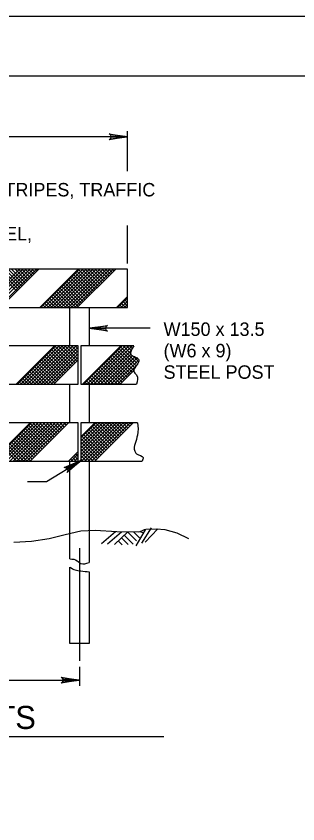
# Model space of a CAD drawing. Extents: x -4 to 901, y -468 to 720.
# Drawn here: x 256.4 to 326.8, y 518.1 to 720 of the extents above; entities that cross this region are included whole.
import ezdxf

# ---------------------------------------------------------------- set-up
doc = ezdxf.new("R2010")
doc.units = 0
for name, color, linetype in [('1', 7, 'Continuous'), ('2', 7, 'Continuous'), ('3', 7, 'Continuous'), ('PLT-BNDY', 7, 'Continuous')]:
    doc.layers.add(name, color=color, linetype=linetype)

msp = doc.modelspace()

# ---------------------------------------------------------------- linework, layer by layer
at = {"layer": '1'}
msp.add_lwpolyline([(822.258, 141.027875), (822.258, 705.027875), (36.258, 705.027875), (36.258, 141.027875), (822.258, 141.027875), (822.258, 167.386875), (622.258, 167.386875), (622.258, 232.064375), (822.258, 232.064375), (822.258, 261.027875), (622.258, 261.027875), (622.258, 141.027875), (701.0595, 141.027875), (701.0595, 167.386875), (701.0595, 141.027875), (778.0595, 141.027875), (778.0595, 167.386875), (778.0595, 155.070375), (822.258, 155.070375)], dxfattribs=at)
at = {"layer": '2'}
for p, q in [((284.2805, 681.251125), (284.2805, 691.305125)), ((284.2805, 689.865125), (140.2805, 689.865125)), ((284.2805, 658.235125), (284.2805, 667.691125)), ((252.5145, 647.195125), (262.1145, 656.795125)), ((262.34125, 647.205125), (271.94125, 656.805125)), ((262.34125, 647.205125), (271.94125, 656.805125)), ((271.7145, 647.195125), (281.3145, 656.795125)), ((281.54125, 647.205125), (284.2805, 649.944375)), ((256.45525, 628.005125), (266.05525, 637.605125)), ((273.00925, 627.995125), (282.60925, 637.595125)), ((265.8285, 627.995125), (271.9685, 634.135125)), ((282.3925, 627.995125), (285.9105, 631.513125)), ((250.3425, 608.795125), (259.9425, 618.395125)), ((259.9425, 608.795125), (269.5425, 618.395125)), ((272.5945, 614.881125), (276.1085, 618.395125)), ((276.1085, 608.795125), (285.7085, 618.395125)), ((269.5425, 608.795125), (271.9685, 611.221125)), ((287.8245, 588.247125), (290.2225, 592.081125)), ((288.6925, 588.561125), (291.8045, 591.841125)), ((277.7945, 588.217125), (281.2285, 591.195125)), ((279.2945, 588.111125), (282.7465, 591.105125)), ((281.0225, 587.963125), (284.3045, 591.143125)), ((282.7425, 589.629125), (284.4085, 587.909125)), ((283.4445, 590.309125), (285.6385, 588.047125)), ((284.2345, 591.145125), (286.4785, 588.829125)), ((285.7885, 591.121125), (287.2525, 589.611125)), ((286.4345, 587.607125), (288.7305, 591.587125)), ((287.3565, 591.177125), (288.3065, 590.855125)), ((281.9525, 588.865125), (282.9045, 587.881125)), ((272.2805, 587.057125), (272.2805, 558.835125)), ((272.2805, 557.395125), (272.2805, 552.577125)), ((152.2805, 554.017125), (272.2805, 554.017125))]:
    msp.add_line(p, q, dxfattribs=at)
for points in [[(279.9205, 690.413125), (280.0845, 690.097125), (284.2805, 689.865125), (279.9205, 690.413125), (279.6985, 690.603125), (284.2805, 689.865125), (280.0865, 689.657125), (279.9345, 689.345125), (284.2805, 689.865125), (279.6985, 689.137125), (279.9345, 689.345125)], [(247.66775, 647.195125), (257.26775, 656.795125)], [(248.51625, 647.195125), (258.11625, 656.795125)], [(249.36475, 647.195125), (258.96475, 656.795125)], [(250.21325, 647.195125), (259.81325, 656.795125)], [(251.06225, 647.195125), (260.66225, 656.795125)], [(251.91075, 647.195125), (261.51075, 656.795125)], [(256.99525, 651.693625), (252.32075, 656.386125)], [(257.42025, 652.117125), (252.74575, 656.809625)], [(257.84525, 652.540625), (253.607, 656.795125)], [(258.27025, 652.964125), (254.454, 656.795125)], [(258.6955, 653.387625), (255.30125, 656.795125)], [(259.1205, 653.810875), (256.14775, 656.795125)], [(259.5455, 654.234375), (256.99475, 656.795125)], [(259.97075, 654.657875), (257.84175, 656.795125)], [(260.39575, 655.081375), (258.6885, 656.795125)], [(260.82075, 655.504625), (259.53525, 656.795125)], [(261.246, 655.928125), (260.38225, 656.795125)], [(261.671, 656.351625), (261.21925, 656.805125)], [(262.63525, 647.205125), (272.23525, 656.805125)], [(262.63525, 647.205125), (272.23525, 656.805125)], [(263.47375, 647.195125), (273.07375, 656.795125)], [(264.32225, 647.195125), (273.92225, 656.795125)], [(265.17075, 647.195125), (274.77075, 656.795125)], [(266.01925, 647.195125), (275.61925, 656.795125)], [(266.86775, 647.195125), (276.46775, 656.795125)], [(267.71625, 647.195125), (277.31625, 656.795125)], [(268.56475, 647.195125), (278.16475, 656.795125)], [(269.41325, 647.195125), (279.01325, 656.795125)], [(270.26225, 647.195125), (279.86225, 656.795125)], [(271.11075, 647.195125), (280.71075, 656.795125)], [(276.19525, 651.693625), (271.5215, 656.385375)], [(276.62025, 652.117125), (271.9605, 656.795125)], [(277.04525, 652.540625), (272.80725, 656.795125)], [(277.47025, 652.964125), (273.654, 656.795125)], [(277.8955, 653.387625), (274.50125, 656.795125)], [(278.3205, 653.810875), (275.34775, 656.795125)], [(278.7455, 654.234375), (276.19475, 656.795125)], [(279.17075, 654.657875), (277.04175, 656.795125)], [(279.59575, 655.081375), (277.8885, 656.795125)], [(280.02075, 655.504625), (278.73525, 656.795125)], [(280.446, 655.928125), (279.58225, 656.795125)], [(280.871, 656.351625), (280.41925, 656.805125)], [(256.57, 651.270125), (251.8955, 655.962625)], [(274.06975, 649.576375), (269.396, 654.268125)], [(274.495, 649.999875), (269.82125, 654.691625)], [(274.92, 650.423375), (270.24625, 655.115125)], [(275.345, 650.846625), (270.67125, 655.538375)], [(275.77025, 651.270125), (271.0965, 655.961875)], [(272.3695, 647.882625), (267.69575, 652.574375)], [(272.7945, 648.306125), (268.12075, 652.997875)], [(273.21975, 648.729375), (268.546, 653.421125)], [(273.64475, 649.152875), (268.971, 653.844625)], [(268.82, 647.195125), (265.5705, 650.457125)], [(269.66675, 647.195125), (265.9955, 650.880625)], [(270.51375, 647.195125), (266.4205, 651.304125)], [(271.3605, 647.195125), (266.84575, 651.727375)], [(271.9445, 647.459125), (267.27075, 652.150875)], [(264.58525, 647.195125), (263.445, 648.339875)], [(265.43225, 647.195125), (263.87, 648.763375)], [(266.27925, 647.195125), (264.29525, 649.186875)], [(267.126, 647.195125), (264.72025, 649.610125)], [(267.97275, 647.195125), (265.14525, 650.033625)], [(281.83525, 647.205125), (284.2805, 649.650375)], [(283.76325, 647.205125), (282.65125, 648.315125)], [(283.76325, 647.205125), (282.65125, 648.315125)], [(282.68325, 647.205125), (284.2805, 648.802125)], [(284.2805, 647.535375), (283.07525, 648.739125)], [(284.2805, 648.384625), (283.50125, 649.163125)], [(284.2805, 649.233875), (283.92525, 649.589125)], [(262.89125, 647.195125), (262.59475, 647.492875)], [(263.7385, 647.195125), (263.02, 647.916375)], [(269.8805, 637.595125), (269.8805, 647.195125), (274.6805, 647.195125), (274.6805, 637.595125)], [(282.06725, 647.205125), (281.80325, 647.467125)], [(282.06725, 647.205125), (281.80325, 647.467125)], [(282.91525, 647.205125), (282.22725, 647.891125)], [(282.91525, 647.205125), (282.22725, 647.891125)], [(283.53125, 647.205125), (284.2805, 647.954375)], [(279.0405, 641.457125), (278.8765, 641.773125), (274.6805, 642.005125), (279.0405, 641.457125), (279.2625, 641.267125), (274.6805, 642.005125), (278.8745, 642.213125), (279.0265, 642.525125), (274.6805, 642.005125), (279.2625, 642.733125), (279.0265, 642.525125)], [(289.882, 642.005125), (274.6805, 642.005125)], [(256.74925, 628.005125), (266.34925, 637.605125)], [(256.74925, 628.005125), (266.34925, 637.605125)], [(257.58775, 627.995125), (267.18775, 637.595125)], [(258.43625, 627.995125), (268.03625, 637.595125)], [(259.28475, 627.995125), (268.88475, 637.595125)], [(260.13325, 627.995125), (269.73325, 637.595125)], [(260.98175, 627.995125), (270.58175, 637.595125)], [(261.83025, 627.995125), (271.43025, 637.595125)], [(262.67875, 627.995125), (271.9685, 637.284875)], [(263.52725, 627.995125), (271.9685, 636.436375)], [(269.47075, 631.637125), (264.779, 636.328875)], [(269.895, 632.061375), (265.20325, 636.753125)], [(270.31925, 632.485625), (265.6275, 637.177375)], [(270.7435, 632.909875), (266.05175, 637.601625)], [(271.1675, 633.334375), (266.90675, 637.595125)], [(271.592, 633.758375), (267.75525, 637.595125)], [(271.9685, 634.230375), (268.60375, 637.595125)], [(271.9685, 635.078875), (269.45225, 637.595125)], [(271.9685, 635.927375), (270.30075, 637.595125)], [(271.9685, 636.775875), (271.13925, 637.605125)], [(285.8245, 637.595125), (272.5945, 637.595125), (272.5945, 627.995125), (286.5225, 627.995125)], [(273.30325, 627.995125), (282.90325, 637.595125)], [(274.15175, 627.995125), (283.75175, 637.595125)], [(275.00025, 627.995125), (284.60025, 637.595125)], [(275.84875, 627.995125), (285.44875, 637.595125)], [(276.69725, 627.995125), (285.187, 636.484875)], [(285.8695, 631.481875), (281.16525, 636.172875)], [(286.109, 632.090375), (281.589, 636.597625)], [(286.3495, 632.697625), (282.01275, 637.022375)], [(286.60025, 633.295125), (282.43625, 637.447375)], [(285.11625, 635.622375), (283.13775, 637.595125)], [(285.17225, 636.413875), (283.98775, 637.595125)], [(285.37275, 637.061125), (284.83725, 637.595125)], [(285.744, 637.538375), (285.687, 637.595125)], [(267.3495, 629.515875), (262.65775, 634.207625)], [(267.77375, 629.940125), (263.082, 634.631875)], [(268.198, 630.364375), (263.50625, 635.056125)], [(268.62225, 630.788625), (263.9305, 635.480375)], [(269.0465, 631.212875), (264.35475, 635.904625)], [(264.37625, 627.995125), (271.9685, 635.587375)], [(265.22475, 627.995125), (271.9685, 634.738875)], [(277.54575, 627.995125), (285.1185, 635.567875)], [(278.39425, 627.995125), (285.516, 635.116875)], [(283.75125, 629.357375), (279.047, 634.048375)], [(279.24275, 627.995125), (286.16125, 634.913625)], [(284.175, 629.782375), (279.47075, 634.473375)], [(284.5985, 630.207125), (279.89425, 634.898125)], [(280.09125, 627.995125), (286.7775, 634.681375)], [(285.02225, 630.632125), (280.318, 635.323125)], [(285.446, 631.056875), (280.74175, 635.747875)], [(286.845, 633.898375), (285.682, 635.057875)], [(264.62725, 627.995125), (260.53625, 632.086125)], [(265.47575, 627.995125), (260.9605, 632.510375)], [(266.0765, 628.242875), (261.38475, 632.934625)], [(266.50075, 628.667125), (261.809, 633.358875)], [(266.925, 629.091375), (262.23325, 633.783125)], [(281.71825, 627.995125), (277.35225, 632.348875)], [(282.48025, 628.082875), (277.776, 632.773875)], [(282.904, 628.507625), (278.19975, 633.198625)], [(283.3275, 628.932625), (278.62325, 633.623625)], [(280.94025, 627.995125), (286.846, 633.900875)], [(281.78875, 627.995125), (286.25225, 632.458625)], [(261.23325, 627.995125), (258.83925, 630.389125)], [(262.08175, 627.995125), (259.2635, 630.813375)], [(262.93025, 627.995125), (259.68775, 631.237625)], [(263.77875, 627.995125), (260.112, 631.661875)], [(277.46975, 627.995125), (275.234, 630.224625)], [(278.31925, 627.995125), (275.6575, 630.649375)], [(279.16925, 627.995125), (276.08125, 631.074375)], [(280.019, 627.995125), (276.505, 631.499125)], [(280.8685, 627.995125), (276.9285, 631.924125)], [(256.99075, 627.995125), (256.718, 628.267875)], [(257.83925, 627.995125), (257.14225, 628.692125)], [(258.68775, 627.995125), (257.5665, 629.116375)], [(259.53625, 627.995125), (257.99075, 629.540625)], [(260.38475, 627.995125), (258.415, 629.964875)], [(269.8805, 618.395125), (269.8805, 627.995125)], [(274.07075, 627.995125), (273.53925, 628.525125)], [(274.9205, 627.995125), (273.963, 628.949875)], [(275.77025, 627.995125), (274.3865, 629.374875)], [(274.6805, 627.995125), (274.6805, 618.395125)], [(276.61975, 627.995125), (274.81025, 629.799625)], [(250.635, 608.795125), (260.237, 618.395125)], [(251.4835, 608.795125), (261.0855, 618.395125)], [(252.33225, 608.795125), (261.93425, 618.395125)], [(253.181, 608.795125), (262.783, 618.395125)], [(254.0295, 608.795125), (263.6315, 618.395125)], [(254.878, 608.795125), (264.48, 618.395125)], [(255.7265, 608.795125), (265.3285, 618.395125)], [(256.57525, 608.795125), (266.17725, 618.395125)], [(257.424, 608.795125), (267.026, 618.395125)], [(258.2725, 608.795125), (267.8745, 618.395125)], [(259.12125, 608.795125), (268.72325, 618.395125)], [(264.2245, 613.077125), (259.4245, 617.877125)], [(264.64875, 613.501375), (259.84875, 618.301375)], [(265.073, 613.925625), (260.6035, 618.395125)], [(265.49725, 614.349875), (261.452, 618.395125)], [(265.92175, 614.774375), (262.301, 618.395125)], [(266.346, 615.198625), (263.1495, 618.395125)], [(266.77025, 615.622875), (263.998, 618.395125)], [(267.1945, 616.047125), (264.8465, 618.395125)], [(267.61875, 616.471375), (265.695, 618.395125)], [(268.043, 616.895625), (266.5435, 618.395125)], [(268.46725, 617.319875), (267.392, 618.395125)], [(268.8915, 617.744125), (268.2405, 618.395125)], [(269.31575, 618.168375), (269.089, 618.395125)], [(286.7545, 618.395125), (272.5945, 618.395125), (272.5945, 608.795125), (287.9145, 608.795125)], [(272.5945, 614.596375), (276.3945, 618.395125)], [(272.5945, 613.748125), (277.24325, 618.395125)], [(272.5945, 612.899375), (278.092, 618.395125)], [(272.5945, 612.051375), (278.9405, 618.395125)], [(272.5945, 609.505875), (281.4865, 618.395125)], [(272.5945, 610.354625), (280.638, 618.395125)], [(272.5945, 611.203125), (279.789, 618.395125)], [(272.73175, 608.795125), (282.335, 618.395125)], [(273.58075, 608.795125), (283.18375, 618.395125)], [(274.42925, 608.795125), (284.0325, 618.395125)], [(275.278, 608.795125), (284.88125, 618.395125)], [(280.56275, 613.247125), (275.7605, 618.047125)], [(280.987, 613.671375), (276.261, 618.395125)], [(281.411, 614.095875), (277.1095, 618.395125)], [(281.83525, 614.520125), (277.95825, 618.395125)], [(282.2595, 614.944625), (278.80725, 618.395125)], [(282.6835, 615.368875), (279.65575, 618.395125)], [(283.10775, 615.793375), (280.50475, 618.395125)], [(283.532, 616.217625), (281.35325, 618.395125)], [(283.956, 616.642125), (282.202, 618.395125)], [(284.38025, 617.066375), (283.05075, 618.395125)], [(284.80425, 617.490875), (283.8995, 618.395125)], [(285.2285, 617.915125), (284.74825, 618.395125)], [(262.5275, 611.380125), (257.7275, 616.180125)], [(262.95175, 611.804375), (258.15175, 616.604375)], [(263.376, 612.228625), (258.576, 617.028625)], [(263.80025, 612.652875), (259.00025, 617.452875)], [(278.442, 611.125375), (273.63975, 615.925375)], [(278.866, 611.549625), (274.06375, 616.349625)], [(279.29025, 611.974125), (274.488, 616.774125)], [(279.7145, 612.398375), (274.91225, 617.198375)], [(280.1385, 612.822875), (275.33625, 617.622875)], [(260.406, 609.258625), (255.606, 614.058625)], [(260.83025, 609.682875), (256.03025, 614.482875)], [(261.25475, 610.107375), (256.45475, 614.907375)], [(261.679, 610.531625), (256.879, 615.331625)], [(262.10325, 610.955875), (257.30325, 615.755875)], [(277.1695, 609.852125), (272.5945, 614.424875)], [(277.5935, 610.276625), (272.79125, 615.076625)], [(278.01775, 610.700875), (273.2155, 615.500875)], [(256.627, 608.795125), (253.48475, 611.937375)], [(257.4755, 608.795125), (253.909, 612.361625)], [(258.324, 608.795125), (254.33325, 612.785875)], [(259.1725, 608.795125), (254.7575, 613.210125)], [(259.98175, 608.834375), (255.18175, 613.634375)], [(276.74525, 609.427875), (272.5945, 613.576625)], [(276.321, 609.003375), (272.5945, 612.728125)], [(275.681, 608.795125), (272.5945, 611.880125)], [(270.186, 608.795125), (271.9685, 610.577125)], [(271.9685, 609.112125), (270.91375, 610.166375)], [(271.9685, 609.961125), (271.33825, 610.590875)], [(271.9685, 610.808875), (271.76225, 611.014875)], [(274.83225, 608.795125), (272.5945, 611.031625)], [(273.98325, 608.795125), (272.5945, 610.183125)], [(259.2545, 603.657125), (264.0545, 603.657125), (272.7345, 609.003125)], [(268.7365, 607.183125), (269.0405, 606.999125), (272.7345, 609.003125), (268.7365, 607.183125), (268.4465, 607.229125), (272.7345, 609.003125), (269.2725, 606.627125), (269.3065, 606.281125), (272.7345, 609.003125), (269.2145, 605.981125), (269.3065, 606.281125)], [(269.8805, 584.369125), (269.8805, 608.795125)], [(270.58825, 608.795125), (270.06525, 609.317875)], [(271.43725, 608.795125), (270.48975, 609.742375)], [(271.03475, 608.795125), (271.9685, 609.728375)], [(273.13475, 608.795125), (272.5945, 609.335125)], [(274.6805, 608.795125), (274.6805, 583.441125)], [(255.8805, 588.549125), (260.2905, 588.813125), (264.7025, 589.477125), (268.6585, 590.407125), (272.5945, 591.333125), (276.1685, 591.571125), (281.6165, 591.185125), (286.9865, 591.101125), (287.4605, 591.229125), (288.1505, 591.569125), (288.4945, 591.717125), (288.8425, 591.797125), (291.5045, 591.867125), (293.5585, 591.671125), (296.6205, 590.903125), (299.5205, 589.477125)], [(274.6805, 581.119125), (274.6805, 563.195125), (269.8805, 563.195125), (269.8805, 582.281125)], [(267.9205, 554.565125), (268.0845, 554.249125), (272.2805, 554.017125), (267.9205, 554.565125), (267.6985, 554.755125), (272.2805, 554.017125), (268.0865, 553.809125), (267.9345, 553.497125), (272.2805, 554.017125), (267.6985, 553.289125), (267.9345, 553.497125)]]:
    msp.add_lwpolyline(points, dxfattribs=at)
for points in [[(140.2805, 656.795125), (140.2805, 647.195125), (284.2805, 647.195125), (284.2805, 656.795125)], [(140.2805, 637.595125), (140.2805, 627.995125), (271.9685, 627.995125), (271.9685, 637.595125)], [(140.2805, 618.395125), (140.2805, 608.795125), (271.9685, 608.795125), (271.9685, 618.395125)]]:
    msp.add_lwpolyline(points, close=True, dxfattribs=at)
for points in [[(285.8245, 637.595125), (285.1285, 635.439125), (286.9865, 634.277125), (286.0585, 631.957125), (285.8245, 631.259125), (286.5225, 630.331125), (286.5225, 627.995125)], [(286.7545, 618.395125), (286.7545, 615.243125), (286.0585, 611.297125), (286.5225, 610.601125), (288.1465, 609.671125), (287.9145, 608.795125)], [(269.8805, 584.369125), (271.6665, 583.905125), (272.5945, 583.209125), (274.6805, 583.441125)], [(269.8805, 582.281125), (271.2005, 581.585125), (272.5945, 581.351125), (274.6805, 581.119125)]]:
    msp.add_spline(points, degree=3, dxfattribs=at)
at = {"layer": '3'}
msp.add_line((131.6125, 539.912125), (293.3405, 539.912125), dxfattribs=at)
at = {"layer": 'PLT-BNDY'}
msp.add_lwpolyline([(-3.742, 720.027875), (837.258, 720.027875), (837.258, 126.027875), (-3.742, 126.027875)], close=True, dxfattribs=at)

# ---------------------------------------------------------------- texts
at = {"layer": '3'}
for s, height, p in [('ALTERNATE RED AND WHITE STRIPES, TRAFFIC', 3.359988, (185.6025, 674.959125)), ('EXTRUDED ALUMINUM CHANNEL,', 3.359988, (186.5185, 663.965125)), ('W150 x 13.5', 3.36, (293.27, 640.096125)), ('(W6 x 9)', 3.36, (293.27, 634.736125)), ('STEEL POST', 3.36, (293.27, 629.376125)), ('ALUMINUM PANEL - STEEL POSTS', 5.76, (133.3825, 541.839125))]:
    msp.add_text(s, height=height, dxfattribs=at).set_placement(p)

doc.saveas('drawing.dxf')
